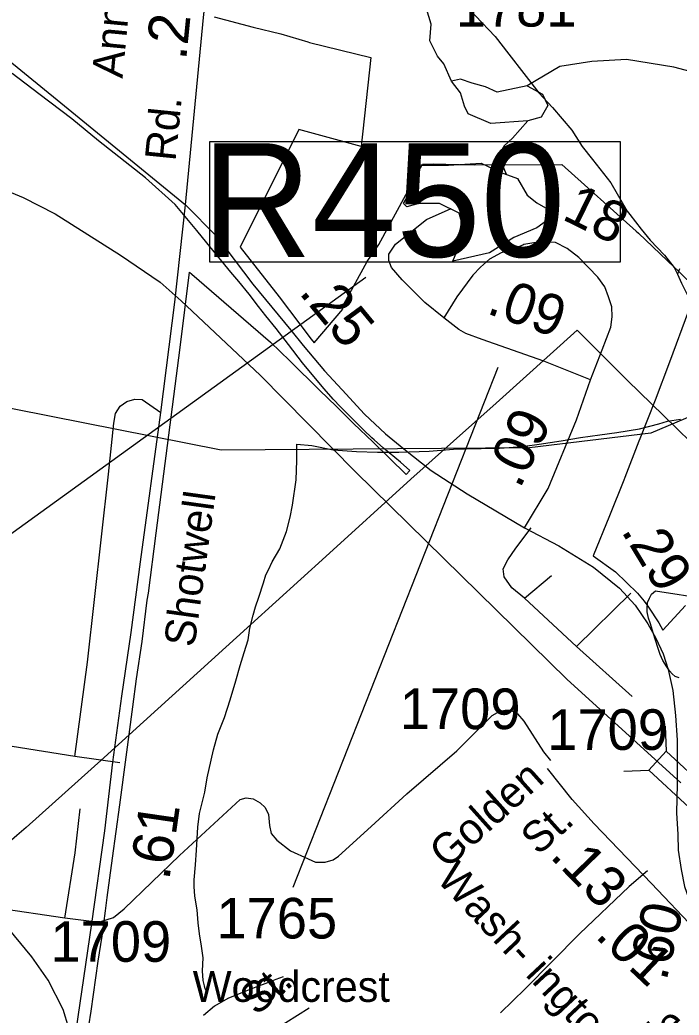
# Model space of a CAD drawing. Extents: x 2169602 to 2449496, y 721995 to 810662.
# Drawn here: x 2398161 to 2400191, y 760928 to 763992 of the extents above; entities that cross this region are included whole.
import ezdxf

# ---------------------------------------------------------------- set-up
doc = ezdxf.new("R2010")
doc.units = 0
doc.layers.add('Default', color=7, linetype='Continuous')

msp = doc.modelspace()

# ---------------------------------------------------------------- linework, layer by layer
at = {"layer": 'Default'}
for p, q in [((2397339.6, 761837.5), (2399226.4, 763199.6)), ((2399632.7, 762921.5), (2399001.9, 761320.4)), ((2399714.7, 762211.2), (2399797.7, 762281.6)), ((2400042.3, 762226.5), (2399875.4, 762062.1)), ((2400148.8, 761817.1), (2400151.7, 761739.9)), ((2398468.7, 761703.9), (2398330, 761723.6)), ((2400020.9, 761679.1), (2400098, 761682))]:
    msp.add_line(p, q, dxfattribs=at)
for points in [[(2396789.6, 764733), (2396958.6, 764680), (2397030.5, 764657.3), (2397200.7, 764582.9), (2397281.4, 764528.7), (2397339.5, 764489.6), (2397377.3, 764463.1), (2397458, 764395), (2397596.7, 764296.6), (2397704, 764208.3), (2397949.9, 764010.3), (2398286.6, 763736.6), (2398670.7, 763422.6)], [(2398670.7, 763422.6), (2398726.8, 763999.1), (2398783.5, 764498.9)], [(2399447, 763880.3), (2399423.5, 763927.4), (2399427.8, 763978.8), (2399412.8, 764025.9), (2399389.2, 764096.5), (2399359.3, 764150), (2399329.3, 764190.7), (2399318.6, 764214.2), (2399282.2, 764244.2), (2399305.8, 764267.7)], [(2399471.9, 764115.4), (2399513.7, 764055.5), (2399564.2, 764004.1), (2399624.7, 763940.2), (2399667.1, 763886.3), (2399759.4, 763766.9), (2399801.6, 763721.6), (2399860.5, 763651.8), (2399892.5, 763602), (2399924.7, 763562.2), (2399981, 763490.4), (2400031.5, 763402.9), (2400039.7, 763392.7), (2400074.1, 763347), (2400102, 763313.1), (2400146.3, 763267.5), (2400176.5, 763229.6), (2400185.9, 763209.2)], [(2398759, 764001.1), (2398879.7, 763969.4), (2398964, 763949.1), (2399047.2, 763924.1), (2399052.7, 763922.4), (2399241.2, 763876.2), (2399211.5, 763602.2), (2399020, 763653.9), (2398839.2, 763291.8), (2398959.2, 763138.6), (2399057.5, 763009.1), (2399067.5, 762997.6), (2399155, 763101.5), (2399152, 763105.2), (2399230.5, 763247.4), (2399266, 763299.9), (2399400.7, 763548), (2399434, 763548.1), (2399512.7, 763546.5), (2399559.7, 763545.3), (2399829.7, 763546.3), (2400059.2, 763341.4), (2400066, 763335.1), (2400177.2, 763229.7), (2400187.5, 763219.9), (2400245.7, 763163)], [(2398759, 764001.1), (2398879.7, 763969.4), (2398964, 763949.1), (2399047.2, 763924.1), (2399052.7, 763922.4), (2399241.2, 763876.2), (2399211.5, 763602.2), (2399020, 763653.9), (2398839.2, 763291.8), (2398959.2, 763138.6), (2399057.5, 763009.1), (2399067.5, 762997.6), (2399155, 763101.5), (2399152, 763105.2), (2399230.5, 763247.4), (2399266, 763299.9), (2399400.7, 763548), (2399434, 763548.1), (2399512.7, 763546.5), (2399559.7, 763545.3), (2399829.7, 763546.3), (2400059.2, 763341.4), (2400066, 763335.1), (2400177.2, 763229.7), (2400187.5, 763219.9), (2400245.7, 763163)], [(2400237.5, 762775.4), (2400104.4, 762719.1), (2399730.4, 762674.2), (2398780.4, 762667.4), (2398038.6, 762813.7), (2397904.5, 762914.9), (2397526.6, 763477), (2397315.2, 763813.3), (2397225.3, 763941.8), (2397159, 763958.9), (2397013.4, 763982.4), (2396906.4, 763976), (2396807.9, 763961), (2396707.3, 763901.1)], [(2396129.6, 763877.6), (2396680.6, 763791.4), (2397139, 763715.8), (2397435.1, 763663.6), (2397561.3, 763644.4), (2397693.5, 763605.1), (2397827.5, 763567.8), (2397896.5, 763550), (2397996.9, 763511.8), (2398101.8, 763473.6), (2398170.6, 763445.2), (2398269.9, 763394.4), (2398470.8, 763267.7), (2398593.3, 763184.4), (2398657.6, 763126.8), (2398901, 762898.2), (2399194.5, 762599.9), (2399845.9, 761961.9), (2400196.3, 761642.8)], [(2399725.3, 763681.2), (2399611.8, 763672.7), (2399541.2, 763702.6), (2399530.5, 763726.2), (2399517.7, 763766.9), (2399489.8, 763803.3), (2399466.3, 763856.8), (2399447, 763880.3)], [(2403253.3, 762662.6), (2403120.3, 762606.3), (2402746.3, 762561.4), (2401796.3, 762554.6), (2401054.4, 762700.9), (2400920.3, 762802), (2400542.4, 763364.1), (2400331, 763700.5), (2400241.1, 763828.9), (2400174.8, 763846.1), (2400029.2, 763869.6), (2399922.2, 763863.2), (2399823.7, 763848.2), (2399723.1, 763788.3)], [(2398366, 760849.7), (2398380.5, 760940.2), (2398402.2, 761093.6), (2398414.2, 761170.9), (2398424.5, 761248.7), (2398429.7, 761289.4), (2398446, 761410.7), (2398468.2, 761575.4), (2398488.5, 761721.7), (2398508.7, 761876.3), (2398520.2, 761962.9), (2398537, 762077.4), (2398553.2, 762205), (2398557, 762227.2), (2398580.7, 762411.9), (2398654.2, 762983.6), (2398683, 763215.1), (2398690.2, 763208.8), (2398932.7, 762999.7), (2398992.2, 762942.2), (2399084.7, 762850.6), (2399134.5, 762802.2), (2399188, 762749.4), (2399248.5, 762691.2), (2399350.7, 762592.5), (2399361.7, 762604.6), (2399333.5, 762629.6), (2399281.2, 762673.1), (2399252, 762698.5), (2399245.2, 762704.9), (2399220.5, 762728.7), (2399196, 762753), (2399171.7, 762776.9), (2399148, 762800.9), (2399126, 762823.9), (2399098.2, 762855.7), (2399061.2, 762899.9), (2399031.7, 762936.2), (2398988.2, 762992.7), (2398950, 763041.6), (2398918.5, 763081.1), (2398895.7, 763109.4), (2398867, 763146.9), (2398835, 763186.5), (2398810.7, 763215.1), (2398801, 763226.4), (2398736.7, 763305.4), (2398706.2, 763343.1), (2398639, 763423.7), (2398547.5, 763505.5), (2398403, 763619.7), (2398320.5, 763686.8), (2398218.7, 763763.8), (2398137.2, 763827.2)], [(2398366, 760849.7), (2398380.5, 760940.2), (2398402.2, 761093.6), (2398414.2, 761170.9), (2398424.5, 761248.7), (2398429.7, 761289.4), (2398446, 761410.7), (2398468.2, 761575.4), (2398488.5, 761721.7), (2398508.7, 761876.3), (2398520.2, 761962.9), (2398537, 762077.4), (2398553.2, 762205), (2398557, 762227.2), (2398580.7, 762411.9), (2398654.2, 762983.6), (2398683, 763215.1), (2398690.2, 763208.8), (2398932.7, 762999.7), (2398992.2, 762942.2), (2399084.7, 762850.6), (2399134.5, 762802.2), (2399188, 762749.4), (2399248.5, 762691.2), (2399350.7, 762592.5), (2399361.7, 762604.6), (2399333.5, 762629.6), (2399281.2, 762673.1), (2399252, 762698.5), (2399245.2, 762704.9), (2399220.5, 762728.7), (2399196, 762753), (2399171.7, 762776.9), (2399148, 762800.9), (2399126, 762823.9), (2399098.2, 762855.7), (2399061.2, 762899.9), (2399031.7, 762936.2), (2398988.2, 762992.7), (2398950, 763041.6), (2398918.5, 763081.1), (2398895.7, 763109.4), (2398867, 763146.9), (2398835, 763186.5), (2398810.7, 763215.1), (2398801, 763226.4), (2398736.7, 763305.4), (2398706.2, 763343.1), (2398639, 763423.7), (2398547.5, 763505.5), (2398403, 763619.7), (2398320.5, 763686.8), (2398218.7, 763763.8), (2398137.2, 763827.2)], [(2399723.1, 763788.3), (2399631.1, 763769), (2399594.7, 763786.1), (2399554, 763796.8), (2399517.7, 763809.7), (2399489.8, 763803.3)], [(2399723.1, 763788.3), (2399770.2, 763762.6), (2399787.4, 763728.3), (2399766, 763691.9), (2399725.3, 763681.2), (2399678.2, 763627.7), (2399652.5, 763604.2), (2399635.4, 763574.2), (2399658.9, 763516.4)], [(2398201, 759070.6), (2398207.5, 759085.3), (2398243.1, 759161.9), (2398280.5, 759275.2), (2398290.2, 759348.7), (2398297.9, 759513.1), (2398280.5, 759699.9), (2398263.3, 759823), (2398247.6, 759977.5), (2398243.8, 760069.3), (2398243.8, 760150.4), (2398253.7, 760296.2), (2398293.5, 760562.9), (2398321.7, 760796.5), (2398382.5, 761209.7), (2398422.9, 761495.4), (2398447.5, 761706.7), (2398475.2, 761909.7), (2398503, 762105.2), (2398532.6, 762323.4), (2398595, 762783.1), (2398637.9, 763122.4), (2398670.7, 763422.6)], [(2398670.7, 763422.6), (2398766.4, 763325.9), (2398878.1, 763178), (2398995.5, 763036.6), (2399033.3, 762989.3), (2399099.5, 762911.2), (2399153.1, 762852.5), (2399222.5, 762777.5), (2399286.8, 762717.6), (2399343.6, 762671.5), (2399427.4, 762604.7), (2399538.4, 762532.1), (2399715, 762428.1)], [(2399466.5, 763074.5), (2399407.9, 763121.8), (2399338.5, 763191.1), (2399305.1, 763229.6), (2399296.9, 763251.1), (2399296.9, 763270), (2399317.7, 763300.9), (2399412.9, 763377.2), (2399489, 763411.1)], [(2399846.2, 763288.3), (2399810.3, 763306.3), (2399780.7, 763308.3), (2399750.3, 763305.9), (2399712.9, 763300.1), (2399709.4, 763298.4), (2399669.6, 763283.2), (2399643.1, 763274.4), (2399607.2, 763254.8), (2399579.7, 763230.8), (2399555.5, 763205.4), (2399506.3, 763139.4), (2399466.5, 763074.5)], [(2399918.1, 762883.4), (2399954.6, 762975.5), (2399981.1, 763045.5), (2399985.5, 763077.6), (2399984.3, 763107.9), (2399974.2, 763138.8), (2399962.2, 763170.3), (2399940.8, 763200), (2399882.1, 763260.5), (2399846.2, 763288.3)], [(2400192.5, 763225.6), (2400185.9, 763209.2)], [(2400185.9, 763209.2), (2400198.6, 763181.7), (2400226.9, 763123.9), (2400265.5, 763052.3), (2400307.9, 762980.6), (2400344.2, 762932.6), (2400376.2, 762885.1), (2400400.8, 762839.2)], [(2400220.5, 763096.4), (2400161.7, 762937.7), (2400117, 762820.7), (2400070.7, 762701.9), (2400067.7, 762694.5), (2400024, 762583.3), (2400020.7, 762575.1), (2399977, 762464.6), (2399927, 762341.2), (2399995.5, 762292), (2400062.7, 762227.2), (2400083.5, 762202.5), (2400097, 762184.1), (2400129.2, 762135), (2400141.2, 762113), (2400211.2, 762189.1)], [(2400220.5, 763096.4), (2400161.7, 762937.7), (2400117, 762820.7), (2400070.7, 762701.9), (2400067.7, 762694.5), (2400024, 762583.3), (2400020.7, 762575.1), (2399977, 762464.6), (2399927, 762341.2), (2399995.5, 762292), (2400062.7, 762227.2), (2400083.5, 762202.5), (2400097, 762184.1), (2400129.2, 762135), (2400141.2, 762113), (2400211.2, 762189.1)], [(2399918.1, 762883.4), (2399774.3, 762940.8), (2399584.5, 763007.6), (2399534, 763025.9), (2399513.2, 763038.5), (2399466.5, 763074.5)], [(2400226.9, 762691.7), (2400142.7, 762773.5), (2400032.7, 762881.6), (2399877.4, 763036.3), (2399628.2, 762811.5), (2399364.7, 762577.8), (2399103.2, 762340.1), (2398871.7, 762130), (2398419.9, 761721.1), (2398179.7, 761504.9), (2398150.9, 761480.6), (2397998.9, 761348.6), (2397859.4, 761221.7), (2397856.7, 761219.3), (2397811.9, 761178.6), (2397720.7, 761095.6), (2397716.4, 761091.6), (2397676.7, 761053.3), (2397637.4, 761018.1), (2397578.4, 760965.3), (2397541.4, 760931.7), (2397427.4, 760826.9)], [(2400226.9, 762691.7), (2400142.7, 762773.5), (2400032.7, 762881.6), (2399877.4, 763036.3), (2399628.2, 762811.5), (2399364.7, 762577.8), (2399103.2, 762340.1), (2398871.7, 762130), (2398419.9, 761721.1), (2398179.7, 761504.9), (2398150.9, 761480.6), (2397998.9, 761348.6), (2397859.4, 761221.7), (2397856.7, 761219.3), (2397811.9, 761178.6), (2397720.7, 761095.6), (2397716.4, 761091.6), (2397676.7, 761053.3), (2397637.4, 761018.1), (2397578.4, 760965.3), (2397541.4, 760931.7), (2397427.4, 760826.9)], [(2399715, 762428.1), (2399787.5, 762548.5), (2399875.2, 762760.4), (2399918.1, 762883.4)], [(2398330, 761723.6), (2398369.3, 762014.6), (2398433.7, 762592.8), (2398450.1, 762750.6), (2398455.6, 762780.1), (2398469.8, 762802), (2398490.5, 762817.3), (2398514.6, 762823.8), (2398537.5, 762822.7), (2398595, 762783.1)], [(2399014, 762685.5), (2399059.9, 762681.4), (2399125.8, 762667.7), (2399197.9, 762662.5), (2399261.9, 762660.6), (2399327.7, 762661.1), (2399421.7, 762663.6), (2399495.9, 762670.2), (2399565.6, 762672.3), (2399581.8, 762672.3), (2399637.8, 762672.7), (2399667.5, 762675.1), (2399715.9, 762679.1), (2399759.8, 762685.5), (2399827.5, 762695.9), (2399887.3, 762706.3), (2399947.4, 762714.7), (2399999.5, 762721), (2400069.2, 762733.2), (2400128.9, 762747.7), (2400155.3, 762755.9), (2400195.1, 762762)], [(2398735.4, 761000.1), (2398731.7, 761008), (2398729.4, 761018.1), (2398725.3, 761034.1), (2398723, 761064), (2398725.1, 761104.3), (2398720.4, 761140.3), (2398714.4, 761178.1), (2398710.3, 761212), (2398706.4, 761252), (2398699.7, 761293.9), (2398697.4, 761323.8), (2398697.4, 761344.1), (2398701.7, 761389.8), (2398705.2, 761435.8), (2398708.7, 761505.9), (2398714.4, 761548), (2398730.2, 761614.2), (2398737.4, 761658.1), (2398749.5, 761712.3), (2398757.3, 761744.3), (2398770.8, 761792.2), (2398790.5, 761844.4), (2398808.6, 761898.4), (2398826.2, 761956.6), (2398839.7, 762004.5), (2398851.6, 762044.4), (2398863.5, 762082.8), (2398869.5, 762118.8), (2398879.1, 762158.7), (2398886.9, 762184.7), (2398896.9, 762214.8), (2398910.7, 762258.6), (2398918.5, 762283), (2398926.3, 762298.8), (2398937.9, 762323), (2398961.5, 762363.2), (2398981.6, 762417), (2398993.1, 762461.1), (2399000.9, 762497.2), (2399012.2, 762575.4), (2399014, 762635.2), (2399014, 762685.5)], [(2399875.4, 762062.1), (2399714.7, 762211.2), (2399676.5, 762242.9), (2399652.4, 762276.7), (2399649.2, 762301.8), (2399663.4, 762329.1), (2399688.5, 762365.2), (2399735.4, 762427.4)], [(2399715, 762428.1), (2399821, 762372), (2399927.5, 762307), (2400007.6, 762242.1), (2400055.5, 762189.7), (2400095.3, 762132.3), (2400119.9, 762088.2), (2400141.9, 762040.3), (2400157.7, 761991.7), (2400171.6, 761927.4), (2400180.4, 761850.4), (2400184.8, 761774.1), (2400184.8, 761725), (2400184.8, 761638.6)], [(2400102.6, 762135.5), (2400096.9, 762149.8), (2400092.6, 762169.5), (2400092.6, 762179.7), (2400094.2, 762197.7), (2400100, 762211.8), (2400106.1, 762223.5), (2400118.2, 762233.8), (2400278, 762208.8)], [(2400191.8, 761966.3), (2400185.7, 761968.1), (2400179.5, 761970.2), (2400169.5, 761978.2), (2400161.3, 761987.9), (2400153.5, 762000.1), (2400141.2, 762019.8), (2400133, 762037.7), (2400125.4, 762059.9), (2400112.7, 762101.6), (2400102.6, 762135.5)], [(2400046.2, 761909), (2399875.4, 762062.1)], [(2398407.5, 761214.7), (2398449, 761228.4), (2398481.8, 761254.6), (2398652.2, 761419.5), (2398838.9, 761591.5), (2398857.5, 761596.9), (2398879.3, 761593.6), (2398901.1, 761581.6), (2398916.4, 761566.3), (2398926.3, 761545.6), (2398929.5, 761511.7), (2398935, 761486.6), (2398952.5, 761465.9), (2398994, 761433.1), (2399048.6, 761409.1), (2399071.5, 761398.2), (2399101, 761398.7), (2399126.1, 761405.3), (2399142.5, 761417.3), (2399242.9, 761507.9), (2399352.1, 761608.4), (2399506.1, 761741.1), (2399568.4, 761803.3), (2399615.3, 761850.3), (2399639.3, 761863.4), (2399655.7, 761866.7), (2399674.3, 761866.7), (2399693.9, 761855.7), (2399712.5, 761832.8), (2399773.7, 761737.8), (2399795.5, 761711.6)], [(2398330, 761723.6), (2398013.3, 761774.4), (2397739.2, 761803.3)], [(2398299.4, 761225.6), (2398089.8, 761256.8), (2397899.8, 761284.1), (2397643.1, 761314.1), (2397612.6, 761326.1), (2397590.7, 761342.5), (2397582, 761362.1), (2397577.6, 761398.2), (2397624.6, 761751.4)], [(2400305.9, 761127.1), (2400240.3, 761191.4), (2400106.6, 761332.7), (2399930, 761516.8), (2399861.9, 761591.3), (2399786.3, 761687.1)], [(2400184.8, 761638.6), (2400183.6, 761550.3), (2400187.2, 761483.8), (2400188.2, 761435.2), (2400197.4, 761376.2), (2400207.5, 761323.2), (2400226.4, 761270.9), (2400245.4, 761231.2), (2400271.2, 761183.9), (2400305.9, 761127.1)], [(2398299.4, 761225.6), (2398331.1, 761427.7), (2398346.4, 761562.5)], [(2398312.5, 760747.1), (2398328.6, 760788.6), (2398328.6, 760830), (2398294.1, 760945.2), (2398248, 761035), (2398197.3, 761106.5), (2398075.2, 761253.9), (2398010.7, 761338), (2397932.4, 761448.5)], [(2400093.6, 761372), (2400037.9, 761323.9), (2399884, 761177.6), (2399716.9, 761008.9), (2399641.5, 760934.1)], [(2398407.5, 761214.7), (2398381.3, 761215.8), (2398299.4, 761225.6)], [(2398971.3, 761045.6), (2398949.6, 761037.6), (2398923.5, 761027.3), (2398887.2, 761013.3), (2398851.7, 760998.8), (2398801.5, 760978.8), (2398760.1, 760954.7), (2398726, 760926.1)], [(2398515.2, 760551.3), (2398639.6, 760657.3), (2398750.1, 760747.1), (2398872.2, 760836.9), (2399051.9, 760949.8)]]:
    msp.add_lwpolyline(points, dxfattribs=at)
for points in [[(2400010.5, 763616.1), (2398745, 763616.1), (2398745, 763247.3), (2400010.5, 763247.3)], [(2399395.7, 763544.3), (2399481.3, 763544.3), (2399581.9, 763550.7), (2399639.7, 763522.8), (2399693.2, 763503.6), (2399723.1, 763452.2), (2399753.1, 763428.7), (2399787.4, 763409.4), (2399793.8, 763381.6), (2399753.1, 763351.6), (2399682.5, 763321.6), (2399607.6, 763274.6), (2399494.1, 763248.9), (2399521.9, 763315.2), (2399521.9, 763366.6), (2399513.4, 763396.6), (2399453.4, 763426.5), (2399389.2, 763426.5), (2399352.8, 763415.8), (2399342.1, 763426.5), (2399370, 763473.6)], [(2400151.7, 761739.9), (2400275.6, 761625.1), (2400222, 761567.1), (2400098, 761682)]]:
    msp.add_lwpolyline(points, close=True, dxfattribs=at)

# ---------------------------------------------------------------- texts
for s, height, rotation, p in [('Annie V.', 95, 84.6147, (2398476.9, 763810.2)), ('.20', 125, 84.2035, (2398672.6, 763865.7)), ('Rd.', 95, 84.2724, (2398639.9, 763554.8)), ('.18', 125, 333.8717, (2399785.1, 763400.1)), ('.25', 125, 309.4845, (2399017.7, 763151.6)), ('.09', 125, 340.5489, (2399594.6, 763089.3)), ('.09', 125, 64.6132, (2399700.7, 762545.3)), ('Shotwell', 95, 82.1202, (2398698.2, 762057.9)), ('.29', 125, 301.2292, (2400010.9, 762418.5)), ('Golden', 95, 41.8513, (2399475.9, 761374.7)), ('.61', 125, 81.775, (2398620.7, 761340.6)), ('St.', 95, 41.8513, (2399757.4, 761416.9)), ('.13', 125, 314.2441, (2399790.2, 761415)), ('Wash- ington', 95, 313.0757, (2399440.5, 761344.4)), ('.60', 125, 76.6763, (2400151.9, 761030.1)), ('.01', 125, 316.6406, (2399929.3, 761168.5)), ('St.', 95, 40.2566, (2398889, 760923.4)), ('Iron- dale', 95, 43.4652, (2399833.2, 760522.2))]:
    msp.add_text(s, height=height, rotation=rotation, dxfattribs=at).set_placement(p)
for s, height, p in [('1781', 125, (2399503.3, 763971.2)), ('R450', 350, (2398721.7, 763262.2)), ('1709', 125, (2399330.9, 761808.2)), ('1709', 125, (2399785.2, 761744.2)), ('1765', 125, (2398766.2, 761163.5)), ('1709', 125, (2398254.9, 761091.8)), ('Woodcrest', 95, (2398693, 760968.3))]:
    msp.add_text(s, height=height, dxfattribs=at).set_placement(p)

doc.saveas('drawing.dxf')
